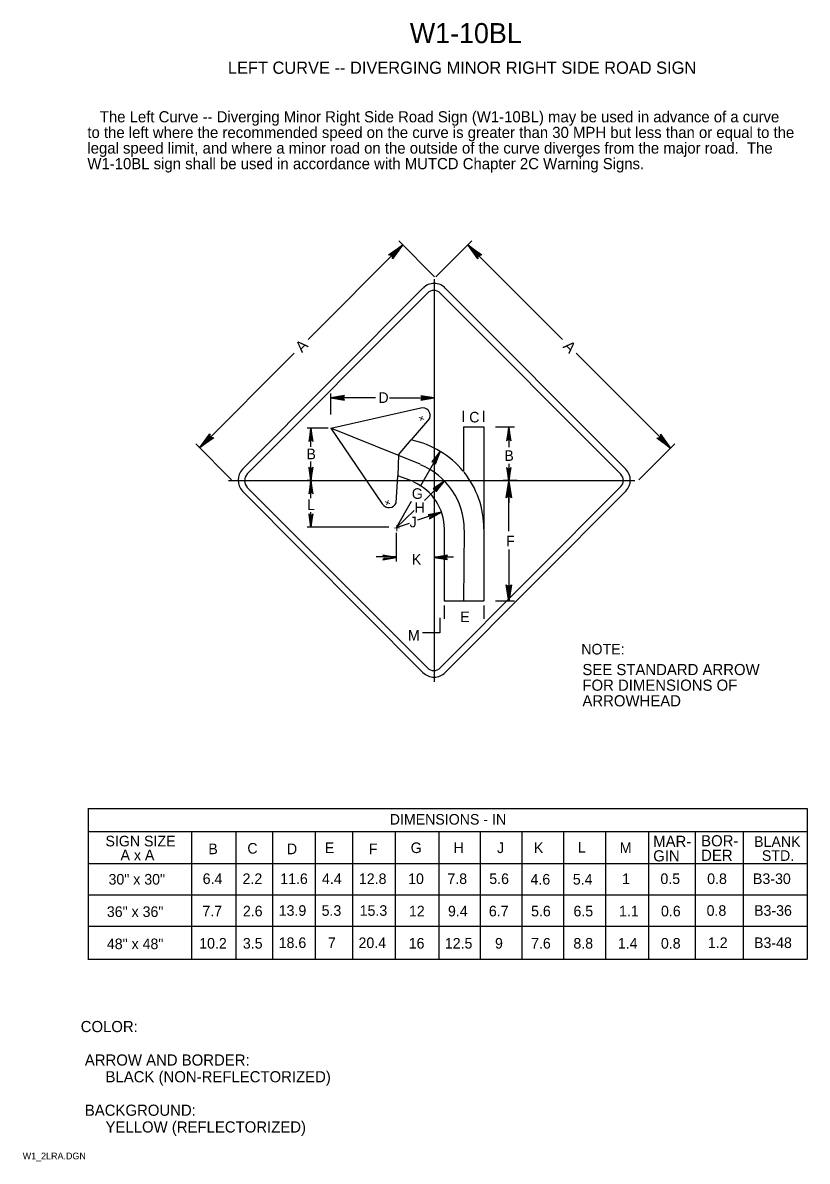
# Model space of a CAD drawing. Extents: x 0.013 to 0.188, y 0.004 to 0.259.
import ezdxf

# ---------------------------------------------------------------- set-up
doc = ezdxf.new("R2010")
doc.units = 0
for name, color, linetype in [('1', 7, 'Continuous'), ('2', 7, 'Continuous'), ('3', 7, 'Continuous')]:
    doc.layers.add(name, color=color, linetype=linetype)

# ---------------------------------------------------------------- blocks, each defined once
blk = doc.blocks.new('RARROW')
at = {"layer": '3'}
for p, q in [((-2.156, 0.28500000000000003), (-2.2665, 0.384625)), ((-2.2665, 0.384625), (0, 0)), ((0, 0), (-2.2665, -0.379125)), ((-2.156, 0.28500000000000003), (-2.075625, 0.12075)), ((0, 0), (-2.156, 0.28500000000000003)), ((-2.14975, -0.2705), (0, 0)), ((-2.075625, 0.12075), (0, 0)), ((0, 0), (-2.074, -0.108)), ((-2.2665, -0.379125), (-2.14975, -0.2705)), ((-2.074, -0.108), (-2.14975, -0.2705))]:
    blk.add_line(p, q, dxfattribs=at)

msp = doc.modelspace()

# ---------------------------------------------------------------- linework, layer by layer
at = {"layer": '3'}
for p, q in [((0.07649568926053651, 0.18811790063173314), (0.09768889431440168, 0.2093111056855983)), ((0.10484834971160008, 0.2021516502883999), (0.09680500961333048, 0.2101949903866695)), ((0.10515165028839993, 0.2021516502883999), (0.11319499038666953, 0.2101949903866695)), ((0.13350431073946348, 0.18811790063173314), (0.11231110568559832, 0.2093111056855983)), ((0.10475, 0.201625), (0.10475, 0.111375)), ((0.06175, 0.159), (0.10225000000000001, 0.199625)), ((0.10725, 0.199625), (0.14775, 0.159)), ((0.06275, 0.15787500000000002), (0.10325000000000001, 0.1985)), ((0.106125, 0.1985), (0.146625, 0.15787500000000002)), ((0.073402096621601, 0.18502431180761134), (0.052188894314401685, 0.1638111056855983)), ((0.136597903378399, 0.18502431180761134), (0.1578111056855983, 0.1638111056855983)), ((0.081625, 0.17125), (0.081625, 0.176)), ((0.091625, 0.17500000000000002), (0.081625, 0.17500000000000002)), ((0.09475, 0.17500000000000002), (0.10475, 0.17500000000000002)), ((0.10475, 0.17525000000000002), (0.10475, 0.17400000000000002)), ((0.081625, 0.16825), (0.10175000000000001, 0.17275000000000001)), ((0.111375, 0.169625), (0.111375, 0.172125)), ((0.115875, 0.169625), (0.115875, 0.172125)), ((0.10375000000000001, 0.170375), (0.099625, 0.165625)), ((0.111375, 0.1685), (0.115875, 0.1685)), ((0.111375, 0.1685), (0.111375, 0.1585)), ((0.115875, 0.1685), (0.115875, 0.1295)), ((0.11850000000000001, 0.1685), (0.12275, 0.1685)), ((0.12154158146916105, 0.16399713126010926), (0.12154158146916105, 0.16849713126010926)), ((0.081, 0.16825), (0.07625, 0.16825)), ((0.077125, 0.164), (0.077125, 0.16825)), ((0.10162500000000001, 0.160125), (0.081625, 0.16825)), ((0.081625, 0.16825), (0.093125, 0.15125)), ((0.059348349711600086, 0.15665165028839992), (0.05130500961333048, 0.16469499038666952)), ((0.09675, 0.16225), (0.099625, 0.165625)), ((0.1506516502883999, 0.15665165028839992), (0.1586949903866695, 0.16469499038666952)), ((0.09675, 0.16225), (0.096625, 0.1575)), ((0.106125, 0.163), (0.10162500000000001, 0.155125)), ((0.077125, 0.1565), (0.077125, 0.16072275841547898)), ((0.12154158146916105, 0.15149713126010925), (0.12154158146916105, 0.16024090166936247)), ((0.058625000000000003, 0.1565), (0.14975, 0.1565)), ((0.077375, 0.1565), (0.07625, 0.1565)), ((0.077125, 0.1525), (0.077125, 0.1565)), ((0.09625, 0.1515), (0.096625, 0.1575)), ((0.100125, 0.15625), (0.096625, 0.1575)), ((0.107, 0.15637500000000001), (0.10262500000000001, 0.152)), ((0.123375, 0.1565), (0.12025, 0.1565)), ((0.1215, 0.145125), (0.1215, 0.1565)), ((0.10225000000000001, 0.1135), (0.06175, 0.154125)), ((0.10325000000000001, 0.1145), (0.06275, 0.155)), ((0.146625, 0.155125), (0.106125, 0.1145)), ((0.14775, 0.154125), (0.10725, 0.1135)), ((0.099625, 0.15175), (0.09625, 0.145875)), ((0.077125, 0.146), (0.077125, 0.14936379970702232)), ((0.10025, 0.14975), (0.09625, 0.145875)), ((0.106375, 0.149375), (0.101, 0.147625)), ((0.094625, 0.146), (0.07625, 0.146)), ((0.099125, 0.146875), (0.09625, 0.145875)), ((0.107, 0.145625), (0.107, 0.1295)), ((0.09625, 0.14475), (0.09625, 0.138375)), ((0.1115, 0.145375), (0.111375, 0.1295)), ((0.1215, 0.14100000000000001), (0.1215, 0.1295)), ((0.09625, 0.139375), (0.09175, 0.139375)), ((0.10475, 0.140125), (0.10475, 0.138375)), ((0.10475, 0.139375), (0.109125, 0.139375)), ((0.107, 0.1295), (0.115875, 0.1295)), ((0.107, 0.1285), (0.107, 0.1255)), ((0.115875, 0.1285), (0.115875, 0.1255)), ((0.11850000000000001, 0.1295), (0.12275, 0.1295)), ((0.027125, 0.083), (0.18837500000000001, 0.083)), ((0.027166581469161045, 0.08299713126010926), (0.027166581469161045, 0.04925)), ((0.18841658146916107, 0.08299713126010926), (0.18841658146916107, 0.04925)), ((0.18837500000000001, 0.07775), (0.027125, 0.07775)), ((0.050381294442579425, 0.07774713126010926), (0.050381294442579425, 0.04925)), ((0.06029158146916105, 0.07774713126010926), (0.06029158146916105, 0.04925)), ((0.06854158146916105, 0.07774713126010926), (0.06854158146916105, 0.04925)), ((0.07804158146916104, 0.07774713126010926), (0.07804158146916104, 0.04925)), ((0.08641658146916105, 0.07774713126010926), (0.08641658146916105, 0.04925)), ((0.09604158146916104, 0.07774713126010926), (0.09604158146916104, 0.04925)), ((0.10579158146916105, 0.07774713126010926), (0.10579158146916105, 0.04925)), ((0.11504158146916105, 0.07774713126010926), (0.11504158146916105, 0.04925)), ((0.12441658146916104, 0.07774713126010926), (0.12441658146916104, 0.04925)), ((0.13379158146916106, 0.07774713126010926), (0.13379158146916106, 0.04925)), ((0.14316658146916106, 0.07774713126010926), (0.14316658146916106, 0.04925)), ((0.15281657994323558, 0.07774713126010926), (0.15281657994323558, 0.04925)), ((0.16329158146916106, 0.07774713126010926), (0.16329158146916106, 0.04925)), ((0.17404158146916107, 0.07774713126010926), (0.17404158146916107, 0.04925)), ((0.027125, 0.07062500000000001), (0.18837500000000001, 0.07062500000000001)), ((0.027125, 0.063625), (0.18837500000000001, 0.063625)), ((0.027125, 0.056625), (0.18837500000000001, 0.056625)), ((0.027125, 0.04925), (0.18837500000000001, 0.04925))]:
    msp.add_line(p, q, dxfattribs=at)
msp.add_lwpolyline([(0.106, 0.12575), (0.106, 0.122375), (0.10212500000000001, 0.122375)], dxfattribs=at)
for centre, radius, start, end in [((0.104772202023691, 0.19718425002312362), 0.0034780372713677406, 44.56843888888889, 135.49785833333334), ((0.1046875, 0.19708563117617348), 0.0020166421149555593, 44.535291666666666, 135.46471111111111), ((0.10212832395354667, 0.17102622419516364), 0.0017475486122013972, 338.12085, 102.38894166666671), ((0.09562520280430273, 0.14564873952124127), 0.0203, 39.47509166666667, 78.2019277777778), ((0.06426195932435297, 0.15655963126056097), 0.003470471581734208, 135.38381666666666, 224.61618055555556), ((0.09575020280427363, 0.14539873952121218), 0.0157686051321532, 0, 67.97055), ((0.09562520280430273, 0.14564873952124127), 0.0203, 0, 38.760247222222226), ((0.14526897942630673, 0.1565624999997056), 0.0034780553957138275, 315.50695833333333, 44.49304444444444), ((0.06433263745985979, 0.15646106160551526), 0.0020894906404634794, 135.70475555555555, 224.93711944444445), ((0.09562520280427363, 0.14564873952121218), 0.01141875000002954, 0, 66.27881944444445), ((0.145225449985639, 0.15650000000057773), 0.0019619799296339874, 315.5069555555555, 44.49304166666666), ((0.09462141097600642, 0.15220111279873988), 0.001773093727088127, 212.439875, 336.70796666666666), ((0.10474999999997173, 0.11589162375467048), 0.003459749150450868, 223.73079444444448, 316.2692083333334), ((0.1046875, 0.11587518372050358), 0.0019893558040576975, 223.73079444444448, 316.2692083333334)]:
    msp.add_arc(centre, radius, start, end, dxfattribs=at)

# ---------------------------------------------------------------- block references
for p, xscale, yscale, rotation in [((0.097625, 0.20925), 0.0016545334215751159, 0.0016366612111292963, 44.999999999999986), ((0.112375, 0.20925), 0.0016545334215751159, 0.0016366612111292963, 135.00000000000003), ((0.081625, 0.17500000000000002), 0.0013236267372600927, -0.001309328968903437, 180), ((0.05225, 0.163875), 0.001654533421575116, 0.001636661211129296, -135), ((0.077125, 0.16825), 0.0013236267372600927, -0.001309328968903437, 90), ((0.1215, 0.168375), 0.0013236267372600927, -0.001309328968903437, 90), ((0.15775, 0.16375), 0.0016545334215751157, 0.001636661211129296, -45), ((0.106125, 0.163), 0.0013236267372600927, -0.0013093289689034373, 60.16446089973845), ((0.077125, 0.1565), 0.0013236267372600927, -0.001309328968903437, -90), ((0.1215, 0.15637500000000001), 0.0013236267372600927, -0.001309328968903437, -90), ((0.077125, 0.1565), 0.0013236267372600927, -0.001309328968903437, 90), ((0.107, 0.15637500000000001), 0.0013236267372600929, -0.001309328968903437, 44.3259631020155), ((0.1215, 0.15637500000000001), 0.0016545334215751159, 0.0016366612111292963, 90), ((0.077125, 0.146), 0.0013236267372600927, -0.001309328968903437, -90), ((0.106375, 0.149375), 0.0013236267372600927, -0.0013093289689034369, 19.698621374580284), ((0.10475, 0.13925), 0.0013236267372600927, -0.001309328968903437, 180), ((0.1215, 0.129375), 0.0016545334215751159, 0.0016366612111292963, -90)]:
    msp.add_blockref('RARROW', p, dxfattribs=dict(at, xscale=xscale, yscale=yscale, rotation=rotation))
at = {"layer": '3', "xscale": 0.0013236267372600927, "yscale": -0.001309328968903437}
for p in [(0.10475, 0.17500000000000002), (0.09625, 0.13925)]:
    msp.add_blockref('RARROW', p, dxfattribs=at)

# ---------------------------------------------------------------- texts
at = {"layer": '1'}
for s, height, p in [('W1-10BL', 0.0045000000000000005, (0.09931068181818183, 0.2545)), ('LEFT CURVE -- DIVERGING MINOR RIGHT SIDE ROAD SIGN', 0.00275025, (0.0585, 0.247625)), ('G', 0.0023752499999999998, (0.09975, 0.152375)), ('H', 0.0023752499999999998, (0.100375, 0.14925)), ('J', 0.0023752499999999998, (0.09925, 0.146)), ('NOTE:', 0.0023752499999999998, (0.13775, 0.11750000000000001)), ('SEE STANDARD ARROW', 0.0024997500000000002, (0.138, 0.112875)), ('FOR DIMENSIONS OF', 0.0024997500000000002, (0.138, 0.109375)), ('ARROWHEAD', 0.0024997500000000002, (0.138, 0.105875)), ('COLOR:', 0.0024997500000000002, (0.025500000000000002, 0.032875)), (' ARROW AND BORDER:', 0.0024997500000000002, (0.025500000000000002, 0.025375)), ('      BLACK (NON-REFLECTORIZED)', 0.0024997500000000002, (0.025500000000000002, 0.021625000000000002)), (' BACKGROUND:', 0.0024997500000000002, (0.025500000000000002, 0.014125)), ('      YELLOW (REFLECTORIZED)', 0.0024997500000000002, (0.025500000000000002, 0.010375)), ('W1_2LRA.DGN', 0.0015, (0.0125, 0.004375))]:
    msp.add_text(s, height=height, dxfattribs=at).set_placement(p)
at = {"layer": '2'}
for s, p in [('   The Left Curve -- Diverging Minor Right Side Road Sign (W1-10BL) may be used in advance of a curve', (0.027, 0.23675025)), ('to the left where the recommended speed on the curve is greater than 30 MPH but less than or equal to the ', (0.027, 0.2332505)), ('legal speed limit, and where a minor road on the outside of the curve diverges from the major road.  The ', (0.027, 0.22975075)), ('W1-10BL sign shall be used in accordance with MUTCD Chapter 2C Warning Signs.', (0.027, 0.226251))]:
    msp.add_text(s, height=0.0024997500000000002, dxfattribs=at).set_placement(p)
at = {"layer": '3'}
for s, height, rotation, p in [('A', 0.0024997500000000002, 45, (0.075125, 0.185)), ('A', 0.0024997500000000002, 315, (0.1335, 0.186375)), ('+', 0.0017775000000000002, 248.12085000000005, (0.101375, 0.171375)), ('+', 0.0017775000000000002, 248.12085000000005, (0.09375, 0.1525))]:
    msp.add_text(s, height=height, rotation=rotation, dxfattribs=at).set_placement(p)
for s, height, p in [('D', 0.0023752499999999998, (0.09225, 0.173875)), ('C', 0.0023752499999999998, (0.112625, 0.1695)), ('B', 0.0023752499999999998, (0.076125, 0.16125)), ('B', 0.0023752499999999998, (0.1205, 0.160875)), ('L', 0.0023752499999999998, (0.07625, 0.149875)), ('+', 0.00200025, (0.095625, 0.144875)), ('F', 0.0023752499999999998, (0.120875, 0.14175000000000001)), ('K', 0.0023752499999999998, (0.09975, 0.137625)), ('E', 0.0023752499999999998, (0.110625, 0.12475)), ('M', 0.0023752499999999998, (0.098875, 0.120625)), ('DIMENSIONS - IN', 0.0023752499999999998, (0.09479229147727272, 0.079375)), ('SIGN SIZE', 0.0023752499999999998, (0.031058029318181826, 0.0745)), ('MAR-', 0.0024997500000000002, (0.153875, 0.074375)), ('BOR-', 0.0024997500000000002, (0.164625, 0.0745)), ('BLANK', 0.0023752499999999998, (0.1765, 0.074375)), ('B', 0.0023752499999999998, (0.054125, 0.07275)), ('C', 0.0023752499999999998, (0.062875, 0.072875)), ('D', 0.0023752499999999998, (0.07175000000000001, 0.07275)), ('E', 0.0023752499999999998, (0.08025, 0.073)), ('F', 0.0023752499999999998, (0.090125, 0.07275)), ('G', 0.0023752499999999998, (0.0995, 0.073)), ('H', 0.0023752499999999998, (0.109125, 0.073)), ('J', 0.0023752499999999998, (0.11887500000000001, 0.073)), ('K', 0.0023752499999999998, (0.12712500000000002, 0.073)), ('L', 0.0023752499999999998, (0.137, 0.073125)), ('M', 0.0023752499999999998, (0.146375, 0.073)), ('A x A', 0.0023752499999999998, (0.034433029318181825, 0.07137500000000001)), ('GIN', 0.0024997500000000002, (0.153875, 0.07112500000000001)), ('DER', 0.0024997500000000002, (0.164625, 0.07125000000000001)), ('STD.', 0.0023752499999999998, (0.17825, 0.07125000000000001)), ('30" x 30"', 0.0023752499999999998, (0.03174541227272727, 0.065937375)), ('6.4', 0.0023752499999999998, (0.05285699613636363, 0.066062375)), ('2.2', 0.0023752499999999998, (0.06179497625, 0.066062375)), ('11.6', 0.0023752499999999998, (0.0702396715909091, 0.066062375)), ('4.4', 0.0023752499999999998, (0.07960699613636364, 0.066062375)), ('12.8', 0.0023752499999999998, (0.08788578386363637, 0.066062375)), ('10', 0.0023752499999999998, (0.09892225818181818, 0.066062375)), ('7.8', 0.0023752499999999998, (0.10773055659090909, 0.066062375)), ('5.6', 0.0023752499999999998, (0.1171185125, 0.066062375)), ('4.6', 0.0023752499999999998, (0.1263685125, 0.065937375)), ('5.4', 0.0023752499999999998, (0.13585699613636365, 0.065937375)), ('1', 0.0023752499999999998, (0.14689395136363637, 0.066062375)), ('0.5', 0.0023752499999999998, (0.1554963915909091, 0.066062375)), ('0.8', 0.0023752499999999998, (0.1659805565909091, 0.066062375)), ('B3-30', 0.0023752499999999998, (0.17624638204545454, 0.066062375)), ('13.9', 0.0023752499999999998, (0.06990233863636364, 0.05893737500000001)), ('5.3', 0.0023752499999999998, (0.0795280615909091, 0.05893737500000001)), ('15.3', 0.0023752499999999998, (0.08805828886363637, 0.05893737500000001)), ('0.8', 0.0023752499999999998, (0.1658555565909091, 0.05893737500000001)), ('B3-36', 0.0023752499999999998, (0.17650142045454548, 0.05893737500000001)), ('36" x 36"', 0.0023752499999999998, (0.03137041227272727, 0.05868737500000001)), ('7.7', 0.0023752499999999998, (0.05277914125, 0.05881237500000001)), ('2.6', 0.0023752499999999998, (0.0618685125, 0.05881237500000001)), ('12', 0.0023752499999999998, (0.09910376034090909, 0.05881237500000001)), ('9.4', 0.0023752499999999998, (0.10785699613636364, 0.05881237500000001)), ('6.7', 0.0023752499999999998, (0.11702914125, 0.05881237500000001)), ('5.6', 0.0023752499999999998, (0.1264935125, 0.05881237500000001)), ('6.5', 0.0023752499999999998, (0.1359963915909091, 0.05881237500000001)), ('1.1', 0.0023752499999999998, (0.14620632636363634, 0.05881237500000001)), ('0.6', 0.0023752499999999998, (0.1556185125, 0.05881237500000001)), ('48" x 48"', 0.0023752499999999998, (0.03137041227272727, 0.05146755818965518)), ('10.2', 0.0023752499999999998, (0.05207520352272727, 0.05159255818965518)), ('3.5', 0.0023752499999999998, (0.06187139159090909, 0.05159255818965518)), ('18.6', 0.0023752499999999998, (0.06989873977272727, 0.05171755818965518)), ('7', 0.0023752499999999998, (0.08093269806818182, 0.05171755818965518)), ('20.4', 0.0023752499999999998, (0.0877962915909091, 0.05171755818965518)), ('16', 0.0023752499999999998, (0.0990522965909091, 0.05159255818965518)), ('12.5', 0.0023752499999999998, (0.10715161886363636, 0.05159255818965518)), ('9', 0.0023752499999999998, (0.11840066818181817, 0.05159255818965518)), ('7.6', 0.0023752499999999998, (0.1264935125, 0.05159255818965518)), ('8.8', 0.0023752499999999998, (0.1359805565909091, 0.05159255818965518)), ('1.4', 0.0023752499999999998, (0.14594792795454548, 0.05159255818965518)), ('0.8', 0.0023752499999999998, (0.1556055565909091, 0.05159255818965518)), ('1.2', 0.0023752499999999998, (0.16613590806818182, 0.05171755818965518)), ('B3-48', 0.0023752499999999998, (0.17648846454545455, 0.05171755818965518))]:
    msp.add_text(s, height=height, dxfattribs=at).set_placement(p)

doc.saveas('drawing.dxf')
